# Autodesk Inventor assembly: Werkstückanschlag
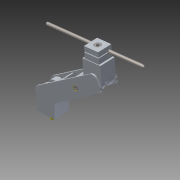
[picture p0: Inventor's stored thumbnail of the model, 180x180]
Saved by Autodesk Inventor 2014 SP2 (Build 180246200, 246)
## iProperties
Created: 2015-07
Part Number: Werkstückanschlag
Document SubType Name: Assembly
Designer: e_krauts
Author: e_krauts
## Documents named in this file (10)
- Z:\VDW-Nachwuchsstiftung Intern\Mitarbeiter Ablage\Steffen Krauth\IVCAM\Werkstückanschlag\Werkstückanschlag.iam
- Z:\VDW-Nachwuchsstiftung Intern\Mitarbeiter Ablage\Steffen Krauth\IVCAM\Werkstückanschlag\Fuß.ipt
- Z:\VDW-Nachwuchsstiftung Intern\Mitarbeiter Ablage\Steffen Krauth\IVCAM\Werkstückanschlag\Bolzen.ipt
- Z:\VDW-Nachwuchsstiftung Intern\Mitarbeiter Ablage\Steffen Krauth\IVCAM\Werkstückanschlag\Seitenteil.ipt
- Z:\VDW-Nachwuchsstiftung Intern\Mitarbeiter Ablage\Steffen Krauth\IVCAM\Werkstückanschlag\Bolzen_Bolzen mit Gewinde.ipt
- Z:\VDW-Nachwuchsstiftung Intern\Mitarbeiter Ablage\Steffen Krauth\IVCAM\Werkstückanschlag\Zylinderschraube ISO 4762 M8 x 55.ipt
- Z:\VDW-Nachwuchsstiftung Intern\Mitarbeiter Ablage\Steffen Krauth\IVCAM\Werkstückanschlag\Zylinderschraube ISO 10642 - M5 x 30.ipt
- Z:\VDW-Nachwuchsstiftung Intern\Mitarbeiter Ablage\Steffen Krauth\IVCAM\Werkstückanschlag\Nadelhalterung.ipt
- Z:\VDW-Nachwuchsstiftung Intern\Mitarbeiter Ablage\Steffen Krauth\IVCAM\Werkstückanschlag\Nadelhalterung_Nadelhalterung Oberteil.ipt
- Z:\VDW-Nachwuchsstiftung Intern\Mitarbeiter Ablage\Steffen Krauth\IVCAM\Werkstückanschlag\Anschlagsnadel.ipt
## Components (13 placed, 9 different names)
1. Fuß — Passend:6, Passend:7, Passend:16
2. Bolzen:1 — Passend:2, Passend:5, Passend:7, Passend:8, Passend:10, Passend:15
3. Seitenteil:1 — Passend:14, Passend:15, Passend:16, Passend:17, Passend:19, Tangential:2
4. Seitenteil:2 — Passend:2, Passend:3, Passend:8, Passend:13, Tangential:1, Passend:18, Passend:20
5. Bolzen_Bolzen mit Gewinde:1 — Passend:3, Passend:12, Passend:14, Passend:17, Passend:18
6. Zylinderschraube ISO 4762 M8 x 55:1 — Passend:5, Passend:6, Passend:10
7. Zylinderschraube ISO 4762 M8 x 55:2 — Passend:12, Passend:21, Passend:25
8. Zylinderschraube ISO 10642 - M5 x 30:1 — Passend:13, Tangential:1
9. Zylinderschraube ISO 10642 - M5 x 30:2 — Passend:19, Tangential:2
10. Fuß:3 — Passend:20, Passend:21, Passend:22, Passend:23, Winkel:1
11. Nadelhalterung:1 — Passend:22, Passend:23, Winkel:1, Passend:24, Winkel:2, Tangential:5
12. Nadelhalterung_Nadelhalterung Oberteil:1 — Passend:24, Winkel:2, Tangential:3, Tangential:4, Passend:25
13. Anschlagsnadel:1 — Tangential:3, Tangential:4, Tangential:5
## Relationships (28: Mate 21, Tangent 5, Angle 2)
- Passend:2 [Mate]: Bolzen:1 ↔ Seitenteil:2
- Passend:3 [Mate]: Seitenteil:2 ↔ Bolzen_Bolzen mit Gewinde:1
- Passend:5 [Mate]: Bolzen:1 ↔ Zylinderschraube ISO 4762 M8 x 55:1
- Passend:6 [Mate]: Fuß ↔ Zylinderschraube ISO 4762 M8 x 55:1
- Passend:7 [Mate]: Fuß ↔ Bolzen:1
- Passend:8 [Mate]: Bolzen:1 ↔ Seitenteil:2
- Passend:10 [Mate]: Bolzen:1 ↔ Zylinderschraube ISO 4762 M8 x 55:1
- Passend:12 [Mate]: Bolzen_Bolzen mit Gewinde:1 ↔ Zylinderschraube ISO 4762 M8 x 55:2
- Passend:13 [Mate]: Seitenteil:2 ↔ Zylinderschraube ISO 10642 - M5 x 30:1
- Tangential:1: Seitenteil:2 ↔ Zylinderschraube ISO 10642 - M5 x 30:1
- Passend:14 [Mate]: Seitenteil:1 ↔ Bolzen_Bolzen mit Gewinde:1
- Passend:15 [Mate]: Bolzen:1 ↔ Seitenteil:1
- Passend:16 [Mate]: Fuß ↔ Seitenteil:1
- Passend:17 [Mate]: Seitenteil:1 ↔ Bolzen_Bolzen mit Gewinde:1
- Passend:18 [Mate]: Seitenteil:2 ↔ Bolzen_Bolzen mit Gewinde:1
- Passend:19 [Mate]: Seitenteil:1 ↔ Zylinderschraube ISO 10642 - M5 x 30:2
- Tangential:2: Seitenteil:1 ↔ Zylinderschraube ISO 10642 - M5 x 30:2
- Passend:20 [Mate]: Seitenteil:2 ↔ Fuß:3
- Passend:21 [Mate]: Zylinderschraube ISO 4762 M8 x 55:2 ↔ Fuß:3
- Passend:22 [Mate]: Fuß:3 ↔ Nadelhalterung:1
- Passend:23 [Mate]: Fuß:3 ↔ Nadelhalterung:1
- Winkel:1 [Angle]: Fuß:3 ↔ Nadelhalterung:1
- Passend:24 [Mate]: Nadelhalterung:1 ↔ Nadelhalterung_Nadelhalterung Oberteil:1
- Winkel:2 [Angle]: Nadelhalterung:1 ↔ Nadelhalterung_Nadelhalterung Oberteil:1
- Tangential:3: Nadelhalterung_Nadelhalterung Oberteil:1 ↔ Anschlagsnadel:1
- Tangential:4: Nadelhalterung_Nadelhalterung Oberteil:1 ↔ Anschlagsnadel:1
- Tangential:5: Nadelhalterung:1 ↔ Anschlagsnadel:1
- Passend:25 [Mate]: Zylinderschraube ISO 4762 M8 x 55:2 ↔ Nadelhalterung_Nadelhalterung Oberteil:1
